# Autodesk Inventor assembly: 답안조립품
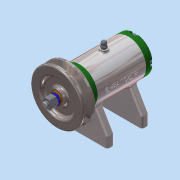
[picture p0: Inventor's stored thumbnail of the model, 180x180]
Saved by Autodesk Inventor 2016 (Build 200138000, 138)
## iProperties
Created: 2018-05
Part Number: 답안조립품
Material: 일반
Document SubType Name: Assembly
Designer: 605-17
Author: 605-17
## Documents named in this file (16)
- C:\Users\605-17\Desktop\480507V1008\답안조립품.iam
- C:\Users\605-17\Desktop\480507V1008\본체.ipt
- C:\Users\605-17\Desktop\480507V1008\V벨트풀리.ipt
- C:\Users\605-17\Desktop\480507V1008\너트 M8.ipt
- C:\Users\605-17\Desktop\480507V1008\니플 M6x0.75.ipt
- C:\Users\605-17\Desktop\480507V1008\뒤커버.ipt
- C:\Users\605-17\Desktop\480507V1008\베어링 6002.ipt
- C:\Users\605-17\Desktop\480507V1008\볼트 M4x12.ipt
- C:\Users\605-17\Desktop\480507V1008\볼트 M6x8.ipt
- C:\Users\605-17\Desktop\480507V1008\스프링와셔 8.ipt
- C:\Users\605-17\Desktop\480507V1008\앞커버.ipt
- C:\Users\605-17\Desktop\480507V1008\오일 실 15 25 7.ipt
- C:\Users\605-17\Desktop\480507V1008\와셔 6x11.5.ipt
- C:\Users\605-17\Desktop\480507V1008\와셔 8x17.ipt
- C:\Users\605-17\Desktop\480507V1008\축.ipt
- C:\Users\605-17\Desktop\480507V1008\키 3x3x12.ipt
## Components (1 placed, 1 different names)
1. V벨트풀리:1 — 각도:2
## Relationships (1: Angle 1)
- 각도:2 [Angle]: V벨트풀리:1
